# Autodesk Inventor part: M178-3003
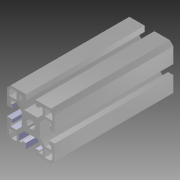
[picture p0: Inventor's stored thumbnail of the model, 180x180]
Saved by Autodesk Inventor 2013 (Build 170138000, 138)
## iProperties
Created: 2004-10
Material: Aluminium - 6061
Document SubType Name: Modeling
Designer: Autodesk, Inc.
Manufacturer: Standard
Standards Organization: Custom
Description: HUTCH, OVERHANG, STRAIGHT BAR
Stock Number: 10-040
Catalog Web Link: http://www.parker.com/ead/cm1.asp?cmid=809
Vendor: PARKER IPS
Part Number: M178-3003
Mass: 179.948 g
Surface Area: 483.565 cm^2
Volume: 66.4013 cm^3
Density: 2.71 g/cm^3
CAGE: 1LJX3
Dept. ID: Product Design
Description #2: ---
Finish #1: ---
Finish #2: ---
Material ID: ---
Project Number: ---
Length: 417.200 mm
Author: Autodesk, Inc.
Revision Number: A
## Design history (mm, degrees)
derived "40 Series Profiles.ipt"
feature "IPS40SeriesCutout1"
body "Solid1"
tag "TaggingFeature2"
sketch "Sketch1"
  geometry: L1 (20, 158.6)-(-1, 158.6) reference; L2 (-1, -258.6)-(-1, 158.6) reference; L3 (7, 158.6)-(7, -258.6) reference; L4 (-1, 138.6)-(7, 138.6); C1 r 10 at (3, 138.6)
  constraints: 2 end point, 2 point on line, 1 centre point, 1 midpoint, 1 perpendicular
  dimensions: "d0" = 20 distance between parallel lines of L4 L1; "d1" = 20 diameter of C1
feature "Solid1::40 Series Profiles.ipt" dims "ScaleForDerivedMember" = 10
other parameters: "Length" = 417.2
